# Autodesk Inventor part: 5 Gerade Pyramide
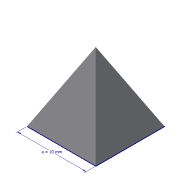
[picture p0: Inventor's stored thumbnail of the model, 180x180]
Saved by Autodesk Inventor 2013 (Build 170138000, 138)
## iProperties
Created: 2012-10
Part Number: 5 Gerade Pyramide
Material: Allgemein
Vendor: www.inventor-faq.de
Document SubType Name: Modeling
Designer: Administrator
Manufacturer: www.inventor-faq.de
Density: 1 g/cm^3
RuleStatus: InUse
AfterDocOpen0: inventorfaq
BeforeDocSave0: inventorfaq
Winkel_Extrusion: -26,56505118 grd
Author: Administrator
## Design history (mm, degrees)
sketch "Skizze1"
  geometry: L1 (-5, 5)-(5, 5); L2 (5, 5)-(5, -5); L3 (5, -5)-(-5, -5); L4 (-5, -5)-(-5, 5); L5 (-5, 5)-(5, -5); L6 (5, 5)-(-5, -5); 1 further point
  constraints: 12 end point, 2 midpoint, 2 parallel, 2 perpendicular, 1 horizontal
  dimensions: "a" = 10 distance of L2.end L3.end
extrude "Extrusion1" new body sketch "Skizze1" distance "d2" = 10 (= h_pyramide); taper "d3" = -26.5651 deg (= Winkel_Extrusion)
node "Volumenkörper1"
other parameters: "Winkel_Extrusion" = -26.5651 deg (computed from h_pyramide, a) [user parameter; used in 1 equation term], "h_pyramide" = 10 [user parameter; used in 2 equation terms]
